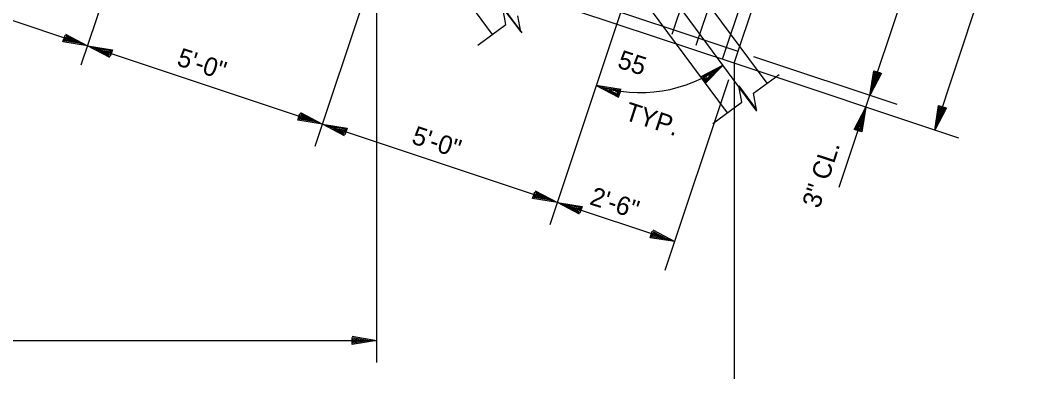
# Model space of a CAD drawing. Extents: x 6 to 106, y 3 to 74.
# Drawn here: x 51.98 to 72.23, y 38.21 to 45.46 of the extents above; entities that cross this region are included whole.
import ezdxf

# ---------------------------------------------------------------- set-up
doc = ezdxf.new("R2010")
doc.units = 0
for name, color, linetype in [('Level 13', 7, 'Continuous'), ('Level 22', 7, 'Continuous'), ('Level 25', 7, 'Continuous'), ('Level 44', 7, 'Continuous'), ('Level 50', 7, 'Continuous')]:
    doc.layers.add(name, color=color, linetype=linetype)

msp = doc.modelspace()

# ---------------------------------------------------------------- linework, layer by layer
at = {"layer": 'Level 13'}
for points in [[(61.789, 45.367), (61.73, 45.697), (62.087, 45.216), (62.03, 45.545)], [(66.551, 43.8), (66.492, 44.129), (66.849, 43.648), (66.791, 43.978)]]:
    msp.add_lwpolyline(points, dxfattribs=at)
at = {"layer": 'Level 22'}
for p, q in [((61.519, 45.167), (59.059, 48.483)), ((62.117, 45.201), (59.759, 48.379)), ((67.066, 44.181), (64.606, 47.498)), ((66.263, 43.586), (63.803, 46.902)), ((66.86, 43.62), (64.502, 46.798)), ((61.224, 44.948), (61.789, 45.367)), ((66.791, 43.978), (67.307, 44.36)), ((65.967, 43.367), (66.551, 43.8))]:
    msp.add_line(p, q, dxfattribs=at)
msp.add_arc((64.502, 46.798), 2.806, 251.5656, 306.565, dxfattribs=at)
at = {"layer": 'Level 25'}
for p, q in [((66.479, 44.822), (41.18, 53.255)), ((66.4, 44.585), (41.18, 52.991)), ((65.149, 45.173), (67.58, 52.468)), ((65.633, 44.947), (67.927, 51.83)), ((69.059, 43.698), (71.588, 51.288)), ((66.4, 44.585), (68.553, 51.045)), ((66.162, 44.664), (68.283, 51.026)), ((70.45, 43.235), (72.98, 50.824)), ((53.213, 44.554), (55.015, 49.961)), ((57.935, 42.909), (59.759, 48.379)), ((66.4, 44.585), (67.642, 48.312)), ((53.341, 44.938), (47.649, 46.835)), ((59.18, 38.546), (59.18, 46.836)), ((62.68, 41.331), (64.502, 46.798)), ((58.084, 43.356), (53.341, 44.938)), ((70.938, 43.072), (66.4, 44.585)), ((69.693, 43.75), (66.796, 44.716)), ((65.008, 40.411), (66.29, 44.256)), ((68.965, 43.417), (69.221, 44.185)), ((68.52, 42.083), (69.059, 43.698)), ((62.828, 41.775), (58.084, 43.356)), ((65.2, 40.985), (62.828, 41.775)), ((23.18, 38.991), (59.18, 38.991))]:
    msp.add_line(p, q, dxfattribs=at)
at = {"layer": 'Level 44'}
msp.add_line((66.4, 44.585), (66.4, 38.214), dxfattribs=at)
at = {"layer": 'Level 50'}
for p, q in [((53.21, 44.981), (53.21, 44.981)), ((53.341, 44.938), (53.341, 44.938)), ((53.341, 44.938), (53.341, 44.938)), ((53.473, 44.894), (53.473, 44.894)), ((66.063, 44.462), (66.063, 44.462)), ((66.063, 44.462), (66.063, 44.462)), ((66.174, 44.544), (66.174, 44.544)), ((66.174, 44.544), (66.174, 44.544)), ((63.615, 44.136), (63.615, 44.136)), ((63.615, 44.136), (63.615, 44.136)), ((63.746, 44.092), (63.746, 44.092)), ((63.746, 44.092), (63.746, 44.092)), ((69.182, 44.067), (69.182, 44.067)), ((69.138, 43.936), (69.138, 43.936)), ((69.015, 43.567), (69.015, 43.567)), ((69.059, 43.698), (69.059, 43.698)), ((57.953, 43.4), (57.953, 43.4)), ((58.084, 43.356), (58.084, 43.356)), ((58.084, 43.356), (58.084, 43.356)), ((70.494, 43.366), (70.494, 43.366)), ((58.216, 43.313), (58.216, 43.313)), ((70.45, 43.235), (70.45, 43.235)), ((62.696, 41.819), (62.696, 41.819)), ((62.828, 41.775), (62.828, 41.775)), ((62.828, 41.775), (62.828, 41.775)), ((62.959, 41.731), (62.959, 41.731)), ((65.068, 41.029), (65.068, 41.029)), ((65.2, 40.985), (65.2, 40.985)), ((59.042, 38.991), (59.042, 38.991)), ((59.18, 38.991), (59.18, 38.991))]:
    msp.add_line(p, q, dxfattribs=at)
for points in [[(52.894, 45.174), (53.341, 44.938), (52.842, 45.017), (52.887, 45.151), (53.21, 44.981), (52.871, 45.035), (52.899, 45.121), (53.083, 45.024), (52.899, 45.054), (52.911, 45.089), (52.951, 45.067)], [(53.788, 44.701), (53.341, 44.938), (53.84, 44.858), (53.796, 44.724), (53.473, 44.894), (53.812, 44.84), (53.783, 44.754), (53.599, 44.852), (53.783, 44.821), (53.771, 44.786), (53.731, 44.808)], [(65.823, 44.181), (66.174, 44.544), (65.724, 44.314), (65.808, 44.2), (66.063, 44.462), (65.757, 44.305), (65.811, 44.232), (65.956, 44.382), (65.79, 44.296), (65.812, 44.266), (65.844, 44.3)], [(65.823, 44.181), (66.174, 44.544), (65.724, 44.314), (65.808, 44.2), (66.063, 44.462), (65.757, 44.305), (65.811, 44.232), (65.956, 44.382), (65.79, 44.296), (65.812, 44.266), (65.844, 44.3)], [(69.374, 44.382), (69.138, 43.936), (69.217, 44.435), (69.351, 44.39), (69.182, 44.067), (69.236, 44.406), (69.322, 44.377), (69.224, 44.194), (69.254, 44.377), (69.289, 44.366), (69.268, 44.325)], [(64.114, 44.057), (63.615, 44.136), (64.062, 43.9), (64.107, 44.034), (63.746, 44.092), (64.05, 43.932), (64.079, 44.018), (63.873, 44.05), (64.038, 43.964), (64.05, 44), (64.004, 44.006)], [(64.114, 44.057), (63.615, 44.136), (64.062, 43.9), (64.107, 44.034), (63.746, 44.092), (64.05, 43.932), (64.079, 44.018), (63.873, 44.05), (64.038, 43.964), (64.05, 44), (64.004, 44.006)], [(57.638, 43.593), (58.084, 43.356), (57.585, 43.436), (57.63, 43.57), (57.953, 43.4), (57.614, 43.454), (57.643, 43.54), (57.826, 43.442), (57.643, 43.473), (57.654, 43.508), (57.695, 43.486)], [(68.823, 43.251), (69.059, 43.698), (68.979, 43.199), (68.845, 43.244), (69.015, 43.567), (68.961, 43.228), (68.875, 43.257), (68.973, 43.44), (68.942, 43.257), (68.907, 43.268), (68.929, 43.309)], [(70.686, 43.682), (70.45, 43.235), (70.529, 43.734), (70.663, 43.689), (70.494, 43.366), (70.548, 43.705), (70.634, 43.677), (70.536, 43.493), (70.566, 43.677), (70.602, 43.665), (70.58, 43.624)], [(58.531, 43.12), (58.084, 43.356), (58.584, 43.277), (58.539, 43.143), (58.216, 43.313), (58.555, 43.259), (58.526, 43.173), (58.343, 43.27), (58.526, 43.24), (58.515, 43.205), (58.474, 43.227)], [(62.381, 42.011), (62.828, 41.775), (62.329, 41.855), (62.373, 41.989), (62.696, 41.819), (62.357, 41.873), (62.386, 41.959), (62.57, 41.861), (62.386, 41.892), (62.398, 41.927), (62.438, 41.905)], [(63.275, 41.539), (62.828, 41.775), (63.327, 41.696), (63.282, 41.562), (62.959, 41.731), (63.298, 41.677), (63.27, 41.591), (63.086, 41.689), (63.27, 41.659), (63.258, 41.624), (63.218, 41.645)], [(64.753, 41.221), (65.2, 40.985), (64.7, 41.064), (64.745, 41.198), (65.068, 41.029), (64.729, 41.083), (64.758, 41.169), (64.942, 41.071), (64.758, 41.101), (64.77, 41.137), (64.81, 41.115)], [(58.682, 39.074), (59.18, 38.991), (58.682, 38.908), (58.682, 39.05), (59.042, 38.991), (58.703, 38.935), (58.703, 39.026), (58.908, 38.991), (58.724, 38.962), (58.724, 38.999), (58.77, 38.991)]]:
    msp.add_lwpolyline(points, dxfattribs=at)

# ---------------------------------------------------------------- texts
at = {"layer": 'Level 22'}
for s, rotation, p in [('5\'-0"', 342, (55.123, 44.548)), ('55', 342, (64.02, 44.504)), ('TYP.', 342, (64.163, 43.453)), ('5\'-0"', 342, (59.864, 42.972)), ('3" CL.', 72, (68.118, 41.638)), ('2\'-6"', 342, (63.46, 41.743))]:
    msp.add_text(s, height=0.3733, rotation=rotation, dxfattribs=at).set_placement(p)

doc.saveas('drawing.dxf')
